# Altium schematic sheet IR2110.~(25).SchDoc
size A4
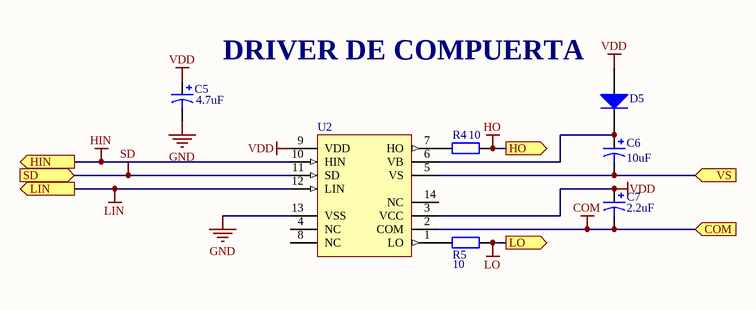
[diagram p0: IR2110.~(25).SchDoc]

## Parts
C5  value 4.7uF  [CAPPR2.5-6.3X5]  (hidden comment: Cap Pol1)
C6  value 10uF  [CAPPR2.5-6.3X5]  (hidden comment: Cap Pol1)
C7  value 2.2uF  [CAPPR2.5-6.3X5]  (hidden comment: Cap Pol1)
D5  Diode  [DO-204AL]  (value not drawn)
R4  value 10  [AXIAL-0.3]  (hidden comment: Res2)
R5  value 10  [AXIAL-0.3]  (hidden comment: Res2)
U2  IR2110  [PDIP14]  (value not drawn)

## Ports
COM (in), HIN (out), HO (out), LIN (out), LO (out), SD (in), VS (in)

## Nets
COM: C7.2 U2.2(COM) ; port COM
GND: C5.2 U2.13(VSS)
HIN: U2.10(HIN) ; port HIN
HO: R4.2 ; port HO
LIN: U2.12(LIN) ; port LIN
LO: R5.2 ; port LO
SD: U2.11(SD) ; port SD
VDD: C5.1 C7.1 D5.1(A) U2.3(VCC) U2.9(VDD)
VS: C6.2 U2.5(VS) ; port VS
NetC6_1: C6.1 D5.2(K) U2.6(VB)
NetR4_1: R4.1 U2.7(HO)
NetR5_1: R5.1 U2.1(LO)

Not connected (* = marked no-connect by the designer): U2 4(NC) 8(NC) 14(NC)

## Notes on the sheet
- (near C5) DRIVER DE COMPUERTA

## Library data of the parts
C5-C7 = Cap Pol1: Polarized Capacitor (Radial)
D5 = Diode: 1N5819
R4 R5 = Res2: Resistor
U2 = IR2110: High and Low Side Driver; Note: Pins 4, 8 and 14 are not connected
